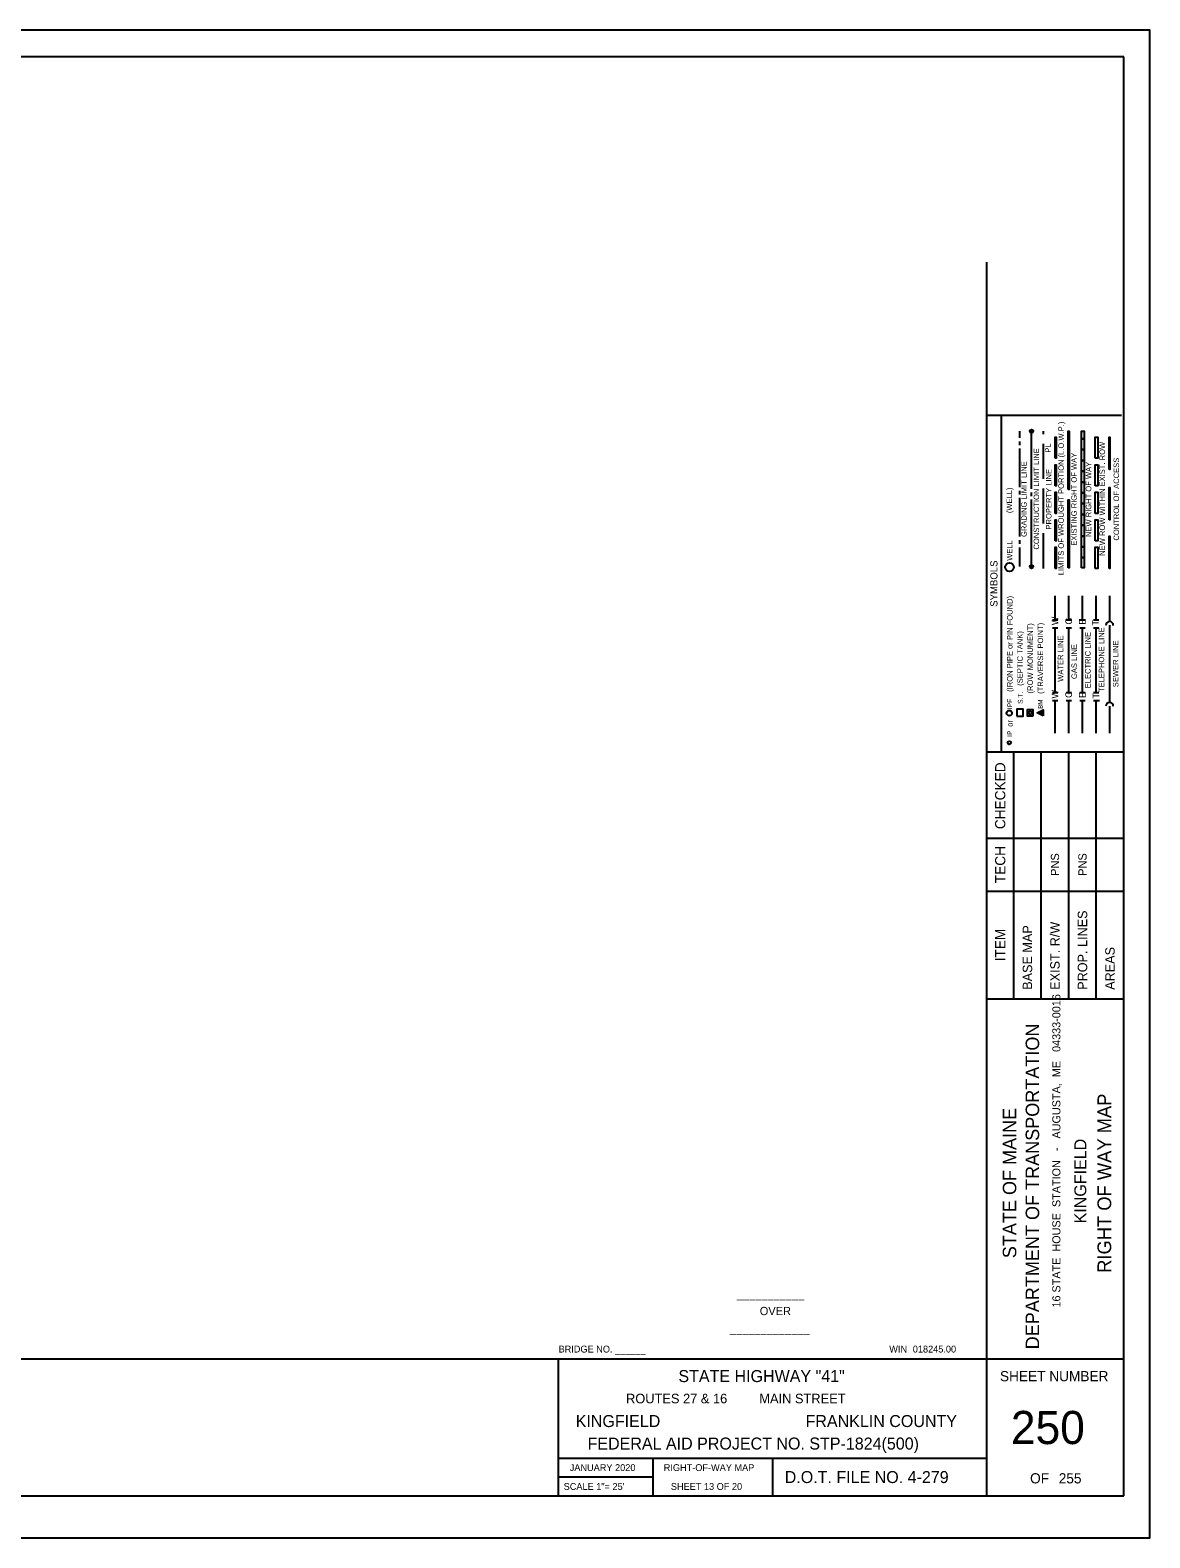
# Model space of a CAD drawing. Extents: x -415 to 435, y -303 to 247.
# Drawn here: x 26 to 435, y -303 to 247 of the extents above; entities that cross this region are included whole.
import ezdxf

# ---------------------------------------------------------------- set-up
doc = ezdxf.new("R2010")
doc.units = 0
for name, color, linetype in [('Border', 7, 'Continuous'), ('BRIDGE_TITLE', 7, 'Continuous'), ('HIGHWAY_TITLE', 7, 'Continuous'), ('PLOT BOUNDARY', 7, 'Continuous')]:
    doc.layers.add(name, color=color, linetype=linetype)

msp = doc.modelspace()

# ---------------------------------------------------------------- linework, layer by layer
at = {"layer": 'Border'}
for p, q in [((425, 237.5), (-375, 237.5)), ((425, -287.49), (425, 237.5)), ((375, -287.5), (375, 162.52)), ((375, 106.81), (424.21, 106.81)), ((380.25, 106.81), (380.25, -16.1)), ((387.03, 98.49), (387.03, 100.86)), ((391.35, 79.88), (391.35, 100.24)), ((395.67, 99.88), (395.67, 100.86)), ((387.03, 95.86), (387.03, 97.18)), ((387.03, 87.51), (387.03, 94.55)), ((395.67, 83.54), (395.67, 96.34)), ((387.03, 80.47), (387.03, 87.51)), ((387.03, 77.85), (387.03, 79.16)), ((391.35, 77.25), (391.35, 78.57)), ((395.67, 67.2), (395.67, 80)), ((387.03, 69.5), (387.03, 76.54)), ((391.35, 52.11), (391.35, 75.94)), ((387.03, 62.46), (387.03, 69.5)), ((387.03, 59.84), (387.03, 61.15)), ((395.67, 50.86), (395.67, 63.66)), ((387.03, 51.49), (387.03, 58.53)), ((399.99, 32.13), (399.99, 40.79)), ((404.97, 32.13), (404.97, 40.79)), ((409.94, 32.13), (409.94, 40.79)), ((414.92, 32.13), (414.92, 40.79)), ((419.9, 31.54), (419.9, 40.79)), ((399.01, 32.13), (400.98, 32.13)), ((399.01, 29.18), (400.98, 29.18)), ((399.99, 5.56), (399.99, 29.18)), ((403.98, 32.13), (405.95, 32.13)), ((403.98, 29.18), (405.95, 29.18)), ((404.97, 17.37), (404.97, 29.18)), ((408.96, 32.13), (410.93, 32.13)), ((408.96, 29.18), (410.93, 29.18)), ((409.94, 17.37), (409.94, 29.18)), ((413.94, 32.13), (415.9, 32.13)), ((413.94, 29.18), (415.9, 29.18)), ((414.92, 17.37), (414.92, 29.18)), ((419.9, 20.32), (419.9, 30.16)), ((404.97, 5.56), (404.97, 17.37)), ((409.94, 5.56), (409.94, 17.37)), ((414.92, 5.56), (414.92, 17.37)), ((419.9, 2.01), (419.9, 20.32)), ((399.01, 5.56), (400.98, 5.56)), ((403.98, 5.56), (405.95, 5.56)), ((408.96, 5.56), (410.93, 5.56)), ((413.94, 5.56), (415.9, 5.56)), ((399.01, 2.61), (400.98, 2.61)), ((399.99, -9.21), (399.99, 2.61)), ((403.98, 2.61), (405.95, 2.61)), ((404.97, -9.21), (404.97, 2.61)), ((408.96, 2.61), (410.93, 2.61)), ((409.94, -9.21), (409.94, 2.61)), ((413.94, 2.61), (416.1, 2.61)), ((414.92, -9.21), (414.92, 2.61)), ((419.9, -9.21), (419.9, 0.64)), ((375, -16.1), (425, -16.1)), ((384.84, -106.22), (384.84, -16.1)), ((394.88, -106.22), (394.88, -16.1)), ((404.92, -106.22), (404.92, -16.1)), ((414.96, -106.22), (414.96, -16.1)), ((375, -47.6), (425, -47.6)), ((375, -66.94), (425, -66.94)), ((375, -106.22), (425, -106.22)), ((-375, -237.49), (425, -237.49)), ((218.75, -287.5), (218.75, -237.49)), ((218.75, -273.75), (375, -273.75)), ((253.12, -273.75), (253.12, -287.5)), ((296.87, -273.75), (296.87, -287.5)), ((253.12, -280.62), (218.75, -280.62)), ((-375, -287.5), (425, -287.5))]:
    msp.add_line(p, q, dxfattribs=at)
for points in [[(404.71, 79.6), (404.71, 100.86), (405.1, 100.86), (405.1, 79.6)], [(409.62, 98.11), (409.62, 100.86), (410.6, 100.86), (410.6, 98.11)], [(399.99, 91.02), (399.99, 98.7), (400.39, 98.7), (400.39, 91.02)], [(409.62, 94.17), (409.62, 98.11), (410.6, 98.11), (410.6, 94.17)], [(409.62, 90.23), (409.62, 94.17), (410.6, 94.17), (410.6, 90.23)], [(414.59, 91.02), (414.59, 98.7), (415.58, 98.7), (415.58, 91.02)], [(419.7, 86.89), (419.7, 98.7), (419.9, 98.7), (419.9, 86.89)], [(399.99, 80.98), (399.99, 88.66), (400.39, 88.66), (400.39, 80.98)], [(409.62, 86.3), (409.62, 90.23), (410.6, 90.23), (410.6, 86.3)], [(414.59, 80.98), (414.59, 88.66), (415.58, 88.66), (415.58, 80.98)], [(409.62, 82.36), (409.62, 86.3), (410.6, 86.3), (410.6, 82.36)], [(399.99, 70.94), (399.99, 78.62), (400.39, 78.62), (400.39, 70.94)], [(409.62, 78.42), (409.62, 82.36), (410.6, 82.36), (410.6, 78.42)], [(409.62, 74.48), (409.62, 78.42), (410.6, 78.42), (410.6, 74.48)], [(414.59, 70.94), (414.59, 78.62), (415.58, 78.62), (415.58, 70.94)], [(419.7, 68.58), (419.7, 80.39), (419.9, 80.39), (419.9, 68.58)], [(404.71, 51.06), (404.71, 75.86), (405.1, 75.86), (405.1, 51.06)], [(409.62, 70.55), (409.62, 74.48), (410.6, 74.48), (410.6, 70.55)], [(399.99, 60.9), (399.99, 68.58), (400.39, 68.58), (400.39, 60.9)], [(409.62, 66.61), (409.62, 70.55), (410.6, 70.55), (410.6, 66.61)], [(409.62, 62.67), (409.62, 66.61), (410.6, 66.61), (410.6, 62.67)], [(414.59, 60.9), (414.59, 68.58), (415.58, 68.58), (415.58, 60.9)], [(409.62, 58.74), (409.62, 62.67), (410.6, 62.67), (410.6, 58.74)], [(419.7, 50.86), (419.7, 62.67), (419.9, 62.67), (419.9, 50.86)], [(399.99, 50.86), (399.99, 58.54), (400.39, 58.54), (400.39, 50.86)], [(409.62, 54.8), (409.62, 58.74), (410.6, 58.74), (410.6, 54.8)], [(414.59, 50.86), (414.59, 58.54), (415.58, 58.54), (415.58, 50.86)], [(409.62, 51.06), (409.62, 54.8), (410.6, 54.8), (410.6, 51.06)]]:
    msp.add_lwpolyline(points, close=True, dxfattribs=at)
for points in [[(385.95, -3.1), (388.31, -3.1), (388.31, -0.54), (385.95, -0.54), (385.95, -3.1)], [(391.98, -2.95), (391.98, -0.7), (389.73, -0.7), (389.73, -2.95), (391.98, -2.95)], [(395.54, -2.89), (393.44, -1.83), (395.54, -0.78), (395.54, -2.89)]]:
    msp.add_lwpolyline(points, dxfattribs=at)
for centre, radius in [((391.35, 100.86), 0.625), ((391.35, 100.86), 0.15), ((391.35, 100.86), 0.05), ((383.29, 51.3), 1.57), ((391.35, 51.49), 0.625), ((391.35, 51.49), 0.15), ((391.35, 51.49), 0.05), ((383.24, -1.91), 0.966), ((390.86, -1.82), 0.563), ((394.86, -1.82), 0.281), ((383.24, -12.74), 0.625)]:
    msp.add_circle(centre, radius, dxfattribs=at)
for centre in [(419.84, 30.08), (419.84, 0.56)]:
    msp.add_arc(centre, 1.35, 0, 180, dxfattribs=at)
at = {"layer": 'PLOT BOUNDARY'}
msp.add_lwpolyline([(-415.47, -302.8), (434.53, -302.8), (434.53, 247.2), (-415.47, 247.2)], close=True, dxfattribs=at)

# ---------------------------------------------------------------- texts
at = {"layer": 'Border'}
for s, height, rotation, p in [('LIMITS OF WROUGHT PORTION (L.O.W.P.)', 1.9996, 90, (403.14, 48.4)), ('PL', 2, 90, (398.35, 93.09)), ('NEW ROW WITHIN EXIST. ROW', 1.9996, 90, (418.14, 55.45)), ('GRADING LIMIT LINE', 1.9996, 90, (389.59, 62.32)), ('CONSTRUCTION LIMIT LINE', 1.9996, 90, (394.11, 57.72)), ('EXISTING RIGHT OF WAY', 1.9996, 90, (407.86, 59.13)), ('NEW RIGHT OF WAY', 1.9996, 90, (413.16, 62.28)), ('CONTROL OF ACCESS', 1.9996, 90, (423.29, 61)), ('PROPERTY LINE', 1.9996, 90, (398.63, 65.04)), ('(WELL)', 2, 90, (384.23, 71.01)), ('WELL', 1.969, 90, (384.36, 53.66)), ('SYMBOLS', 2.614, 90, (378.93, 36.84)), ('(IRON PIPE or PIN FOUND)', 1.9996, 90, (384.41, 5.83)), ('W', 2.46, 90, (401.17, 30.16)), ('(ROW MONUMENT)', 1.9996, 90, (391.85, 5.23)), ('(TRAVERSE POINT)', 1.9996, 90, (395.58, 5.08)), ('G', 2.46, 90, (406.15, 30.36)), ('E', 2.46, 90, (411.13, 30.36)), ('T', 2.46, 90, (415.9, 29.97)), ('TELEPHONE LINE', 1.9996, 90, (417.87, 5.75)), ('(SEPTIC TANK)', 1.9996, 90, (388.13, 8.02)), ('WATER LINE', 2, 90, (402.95, 9.5)), ('GAS LINE', 2, 90, (407.92, 10.48)), ('ELECTRIC LINE', 1.9996, 90, (412.9, 7.13)), ('SEWER LINE', 2, 90, (423.05, 7.53)), ('W', 2.46, 90, (401.17, 3.39)), ('G', 2.46, 90, (406.15, 3.59)), ('E', 2.46, 90, (411.13, 3.59)), ('IPF', 1.749, 90, (384.28, -0.48)), ('S.T.', 1.749, 90, (388.12, 1.42)), ('BM', 1.641, 90, (395.4, -0.38)), ('T', 2.46, 90, (416.1, 3.39)), ('or', 2, 90, (384.47, -6.92)), ('IP', 1.749, 90, (384.28, -10.58)), ('CHECKED', 3.726, 90, (381.78, -44.27)), ('TECH', 3.726, 90, (381.78, -63.99)), ('PROP. LINES', 3.4449, 90, (411.66, -102.87)), ('ITEM', 3.726, 90, (381.78, -92.49)), ('BASE MAP', 3.445, 90, (391.58, -102.87)), ('EXIST. R/W', 3.445, 90, (401.62, -102.87)), ('AREAS', 3.445, 90, (421.7, -102.87)), ('16 STATE  HOUSE  STATION   -   AUGUSTA,  ME   04333-0016', 2.9528, 90, (401.89, -218.78)), ('DEPARTMENT OF TRANSPORTATION', 4.9217, 90, (394.13, -234.02)), ('RIGHT OF WAY MAP', 4.9996, 90, (420.42, -206.11)), ('STATE OF MAINE', 4.9217, 90, (385.79, -200.78)), ('D.O.T. FILE NO. 4-279', 4.375, 360, (301.28, -282.81))]:
    msp.add_text(s, height=height, rotation=rotation, dxfattribs=at).set_placement(p)
for s, height, p in [('SHEET NUMBER', 3.7264, (379.83, -245.67)), ('250', 12.097, (383.82, -268.59)), ('OF', 3.726, (390.83, -282.94)), ('255', 3.726, (401.28, -282.94))]:
    msp.add_text(s, height=height, dxfattribs=at).set_placement(p)
at = {"layer": 'BRIDGE_TITLE'}
for s, height, p in [('___________', 3, (283.84, -215.3)), ('OVER', 3, (292.18, -221.55)), ('_____________', 3, (281.29, -227.8)), ('BRIDGE NO. ______', 2.5, (218.75, -235.19))]:
    msp.add_text(s, height=height, dxfattribs=at).set_placement(p)
at = {"layer": 'HIGHWAY_TITLE'}
for s, height, rotation, p in [('PNS', 3, 90, (401.4, -61.3)), ('PNS', 3, 90, (411.44, -61.3)), ('KINGFIELD', 4.375, 90, (411.35, -188.1)), ('SCALE 1"= 25\'', 2.5, 360, (220.61, -285.31))]:
    msp.add_text(s, height=height, rotation=rotation, dxfattribs=at).set_placement(p)
for s, height, p in [('WIN', 2.5, (339.44, -235.19)), ('018245.00', 2.5, (348.02, -235.19)), ('STATE HIGHWAY "41"', 4.375, (262.49, -245.97)), ('ROUTES 27 & 16         MAIN STREET', 3.5, (243.37, -253.73)), ('KINGFIELD', 4.375, (225, -262.38)), ('FRANKLIN COUNTY', 4.375, (308.88, -262.38)), ('FEDERAL AID PROJECT NO. STP-1824(500)', 4.375, (229.33, -270.58)), ('JANUARY 2020', 2.5, (222.83, -278.43)), ('RIGHT-OF-WAY MAP', 2.5, (257.13, -278.43)), ('SHEET 13 OF 20', 2.5, (259.73, -285.31))]:
    msp.add_text(s, height=height, dxfattribs=at).set_placement(p)

doc.saveas('drawing.dxf')
